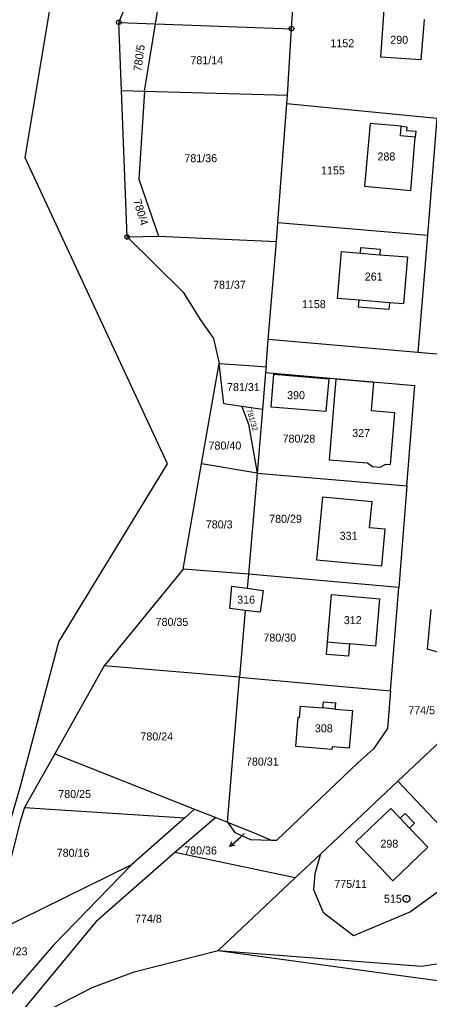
# Model space of a CAD drawing. Extents: x -593358 to -590116, y -1072518 to -1068420.
# Drawn here: x -592030.1 to -591943, y -1070910.9 to -1070702.8 of the extents above; entities that cross this region are included whole.
import ezdxf

# ---------------------------------------------------------------- set-up
doc = ezdxf.new("R2010")
doc.units = 0
for name, color, linetype in [('Parcela KN', 7, 'Continuous'), ('Parcela ZE', 7, 'Continuous'), ('Parcelní číslo', 7, 'Continuous'), ('Parcelní číslo_stavební', 7, 'Continuous'), ('stavby - vnitřní kresba', 7, 'Continuous'), ('Vrstva 16', 7, 'Continuous'), ('Vrstva 17', 7, 'Continuous'), ('Vrstva 24', 7, 'Continuous')]:
    doc.layers.add(name, color=color, linetype=linetype)

msp = doc.modelspace()

# ---------------------------------------------------------------- linework, layer by layer
at = {"layer": 'Parcela KN'}
for p, q in [((-592028.89, -1070732.12), (-592020.01, -1070678.53)), ((-592009.01, -1070703.37), (-592003.67, -1070690.55)), ((-592001.19, -1070703.66), (-591999.04, -1070690.74)), ((-591972.33, -1070704.72), (-591971.79, -1070695.88)), ((-591953.33, -1070710.74), (-591952.61, -1070700.67)), ((-592008.44, -1070717.83), (-592009.01, -1070703.37)), ((-592009.01, -1070703.37), (-592001.19, -1070703.66)), ((-592003.58, -1070717.97), (-592001.19, -1070703.66)), ((-592001.19, -1070703.66), (-591972.33, -1070704.72)), ((-591944.17, -1070702.78), (-591944.88, -1070711.36)), ((-591973.2, -1070718.85), (-591972.33, -1070704.72)), ((-591944.88, -1070711.36), (-591953.33, -1070710.74)), ((-592007.24, -1070748.95), (-592008.44, -1070717.83)), ((-592008.44, -1070717.83), (-592003.58, -1070717.97)), ((-592003.58, -1070717.97), (-592004.78, -1070736.7)), ((-591973.3, -1070720.57), (-591973.2, -1070718.85)), ((-591975.21, -1070745.9), (-591973.3, -1070720.57)), ((-591973.3, -1070720.57), (-591941.43, -1070723.73)), ((-591941.43, -1070723.73), (-591943.47, -1070748.59)), ((-591955.65, -1070724.87), (-591956.79, -1070738.18)), ((-591949.02, -1070725.43), (-591955.65, -1070724.87)), ((-591949.02, -1070725.43), (-591947.84, -1070725.53)), ((-591947.84, -1070725.53), (-591947.91, -1070726.31)), ((-591947.91, -1070726.31), (-591945.95, -1070726.47)), ((-591945.95, -1070726.47), (-591946.05, -1070727.72)), ((-591946.99, -1070739.1), (-591946.05, -1070727.72)), ((-591998.63, -1070797.11), (-592028.89, -1070732.12)), ((-592004.78, -1070736.7), (-592000.6, -1070748.78)), ((-591956.79, -1070738.18), (-591946.99, -1070739.1)), ((-591975.54, -1070749.88), (-591975.21, -1070745.9)), ((-591975.21, -1070745.9), (-591943.47, -1070748.59)), ((-592007.24, -1070748.95), (-592000.6, -1070748.78)), ((-592007.24, -1070748.95), (-591995.35, -1070760.67)), ((-591943.47, -1070748.59), (-591945.51, -1070773.47)), ((-591977.27, -1070770.74), (-591975.54, -1070749.88)), ((-591957.67, -1070752.39), (-591957.58, -1070751.19)), ((-591957.58, -1070751.19), (-591953.48, -1070751.52)), ((-591953.48, -1070751.52), (-591953.58, -1070752.72)), ((-591962.57, -1070762.01), (-591961.67, -1070752.07)), ((-591961.67, -1070752.07), (-591957.67, -1070752.39)), ((-591953.58, -1070752.72), (-591947.68, -1070753.19)), ((-591947.68, -1070753.19), (-591948.53, -1070763.18)), ((-591995.35, -1070760.67), (-591991.75, -1070766.49)), ((-591957.94, -1070762.4), (-591962.57, -1070762.01)), ((-591958.06, -1070763.85), (-591957.94, -1070762.4)), ((-591951.66, -1070764.37), (-591958.06, -1070763.85)), ((-591951.54, -1070762.93), (-591951.66, -1070764.37)), ((-591948.53, -1070763.18), (-591951.54, -1070762.93)), ((-591991.75, -1070766.49), (-591988.9, -1070770.48)), ((-591988.9, -1070770.48), (-591987.72, -1070775.84)), ((-591977.73, -1070776.52), (-591977.27, -1070770.74)), ((-591945.51, -1070773.47), (-591977.27, -1070770.74)), ((-591938.26, -1070774.11), (-591945.51, -1070773.47)), ((-591991.43, -1070797.15), (-591987.72, -1070775.84)), ((-591987.72, -1070775.84), (-591980.35, -1070776.34)), ((-591986.67, -1070784.42), (-591987.72, -1070775.84)), ((-591980.35, -1070776.34), (-591977.73, -1070776.52)), ((-591977.73, -1070776.52), (-591977.84, -1070777.73)), ((-591977.84, -1070777.73), (-591978.5, -1070785.57)), ((-591977.84, -1070777.73), (-591946.12, -1070780.51)), ((-591976.67, -1070785.07), (-591976.09, -1070778.07)), ((-591976.09, -1070778.07), (-591964.41, -1070779.05)), ((-591964.41, -1070779.05), (-591965, -1070786.05)), ((-591962.93, -1070779.16), (-591964.29, -1070796.26)), ((-591954.82, -1070779.87), (-591962.93, -1070779.16)), ((-591955.33, -1070785.89), (-591954.82, -1070779.87)), ((-591947.84, -1070801.82), (-591946.12, -1070780.51)), ((-591982.88, -1070784.95), (-591986.67, -1070784.42)), ((-591978.5, -1070785.57), (-591982.88, -1070784.95)), ((-591982.88, -1070784.95), (-591981.49, -1070788.68)), ((-591978.5, -1070785.57), (-591979.64, -1070799.09)), ((-591965, -1070786.05), (-591976.67, -1070785.07)), ((-591950.4, -1070786.31), (-591955.33, -1070785.89)), ((-591951.31, -1070797.29), (-591950.4, -1070786.31)), ((-591981.49, -1070788.68), (-591979.64, -1070799.09)), ((-592021.75, -1070834.92), (-591998.63, -1070797.11)), ((-591995.32, -1070819.48), (-591991.43, -1070797.15)), ((-591979.64, -1070799.09), (-591991.43, -1070797.15)), ((-591964.29, -1070796.26), (-591956.2, -1070796.89)), ((-591956.2, -1070796.89), (-591955.11, -1070797.68)), ((-591953.5, -1070797.81), (-591952.3, -1070797.2)), ((-591952.3, -1070797.2), (-591951.31, -1070797.29)), ((-591979.64, -1070799.09), (-591981.46, -1070820.57)), ((-591979.64, -1070799.09), (-591947.84, -1070801.82)), ((-591955.11, -1070797.68), (-591953.5, -1070797.81)), ((-591947.84, -1070801.82), (-591949.55, -1070823.39)), ((-591965.76, -1070804.2), (-591967.04, -1070817.5)), ((-591955.22, -1070805.2), (-591965.76, -1070804.2)), ((-591955.74, -1070810.71), (-591955.22, -1070805.2)), ((-591952.44, -1070811.01), (-591955.74, -1070810.71)), ((-591953.17, -1070818.82), (-591952.44, -1070811.01)), ((-591967.04, -1070817.5), (-591953.17, -1070818.82)), ((-591995.32, -1070819.48), (-592012.08, -1070840.02)), ((-591981.46, -1070820.57), (-591995.32, -1070819.48)), ((-591981.46, -1070820.57), (-591981.72, -1070823.56)), ((-591949.55, -1070823.39), (-591981.46, -1070820.57)), ((-591985.45, -1070827.85), (-591985.02, -1070823.1)), ((-591985.02, -1070823.1), (-591981.72, -1070823.56)), ((-591981.72, -1070823.56), (-591978.37, -1070824.02)), ((-591978.37, -1070824.02), (-591978.96, -1070828.67)), ((-591951.33, -1070845.35), (-591949.55, -1070823.39)), ((-591964.69, -1070834.95), (-591963.82, -1070824.9)), ((-591963.82, -1070824.9), (-591953.62, -1070825.78)), ((-591953.62, -1070825.78), (-591954.5, -1070835.89)), ((-591982.14, -1070828.27), (-591985.45, -1070827.85)), ((-591982.14, -1070828.27), (-591983.4, -1070842.44)), ((-591978.96, -1070828.67), (-591982.14, -1070828.27)), ((-591943.42, -1070836.53), (-591942.69, -1070828.05)), ((-592029.91, -1070865.59), (-592021.75, -1070834.92)), ((-591964.89, -1070837.62), (-591964.69, -1070834.95)), ((-591959.98, -1070835.38), (-591960.2, -1070837.97)), ((-591954.5, -1070835.89), (-591959.98, -1070835.38)), ((-591933.56, -1070839.27), (-591943.42, -1070836.53)), ((-591960.2, -1070837.97), (-591964.89, -1070837.62)), ((-592012.08, -1070840.02), (-592022.56, -1070858.71)), ((-591983.4, -1070842.44), (-592012.08, -1070840.02)), ((-591985.92, -1070873.27), (-591983.4, -1070842.44)), ((-591983.4, -1070842.44), (-591951.33, -1070845.35)), ((-591951.33, -1070845.35), (-591951.97, -1070853.34)), ((-591970.64, -1070851), (-591970.44, -1070848.59)), ((-591970.44, -1070848.59), (-591965.65, -1070848.99)), ((-591965.65, -1070848.99), (-591965.54, -1070847.67)), ((-591965.54, -1070847.67), (-591962.98, -1070847.88)), ((-591962.98, -1070847.88), (-591963.09, -1070849.21)), ((-591963.09, -1070849.21), (-591959.38, -1070849.52)), ((-591933.38, -1070849.09), (-591949.74, -1070864.52)), ((-591971.41, -1070857.19), (-591970.92, -1070850.97)), ((-591970.92, -1070850.97), (-591970.64, -1070851)), ((-591959.38, -1070849.52), (-591960.07, -1070857.55)), ((-591951.97, -1070853.34), (-591954.91, -1070857.63)), ((-591963.74, -1070857.83), (-591971.41, -1070857.19)), ((-591963.7, -1070857.27), (-591963.74, -1070857.83)), ((-591960.07, -1070857.55), (-591963.7, -1070857.27)), ((-591954.91, -1070857.63), (-591958.28, -1070860.68)), ((-592022.56, -1070858.71), (-592029, -1070870.12)), ((-592022.56, -1070858.71), (-591992.95, -1070870.47)), ((-591975.43, -1070877.04), (-591958.28, -1070860.68)), ((-592044.25, -1070914.9), (-592029.91, -1070865.59)), ((-591949.74, -1070864.52), (-591966.1, -1070879.95)), ((-591933.14, -1070882.12), (-591949.74, -1070864.52)), ((-592029, -1070870.12), (-592029.94, -1070873.08)), ((-592029, -1070870.12), (-591994.97, -1070872.32)), ((-591992.95, -1070870.47), (-591994.97, -1070872.32)), ((-591992.95, -1070870.47), (-591988.4, -1070872.28)), ((-591958.68, -1070877.44), (-591951.21, -1070870.32)), ((-591951.21, -1070870.32), (-591949.22, -1070872.42)), ((-591949.22, -1070872.42), (-591948.17, -1070871.42)), ((-591948.17, -1070871.42), (-591946.21, -1070873.48)), ((-592029.94, -1070873.08), (-592035.98, -1070896.91)), ((-591994.97, -1070872.32), (-592006.31, -1070882.3)), ((-591988.4, -1070872.28), (-591997.11, -1070879.7)), ((-591988.4, -1070872.28), (-591985.92, -1070873.27)), ((-591985.92, -1070873.27), (-591979.74, -1070875.73)), ((-591985.92, -1070873.27), (-591984.38, -1070875.46)), ((-591946.21, -1070873.48), (-591947.26, -1070874.48)), ((-591984.38, -1070875.46), (-591981.05, -1070876.94)), ((-591979.74, -1070875.73), (-591976.67, -1070877.09)), ((-591947.26, -1070874.48), (-591943.38, -1070878.56)), ((-591981.05, -1070876.94), (-591976.67, -1070877.09)), ((-591976.67, -1070877.09), (-591975.43, -1070877.04)), ((-591950.79, -1070885.67), (-591958.68, -1070877.44)), ((-591997.11, -1070879.7), (-592013.86, -1070894.42)), ((-591971.53, -1070885.07), (-591997.11, -1070879.7)), ((-591966.1, -1070879.95), (-591971.53, -1070885.07)), ((-591967.29, -1070884.16), (-591966.1, -1070879.95)), ((-591943.38, -1070878.56), (-591950.79, -1070885.67)), ((-592006.31, -1070882.3), (-592035.98, -1070896.91)), ((-592006.31, -1070882.3), (-592022.86, -1070899.35)), ((-591933.14, -1070882.12), (-591947.02, -1070892.31)), ((-591967.58, -1070887.6), (-591967.29, -1070884.16)), ((-591971.53, -1070885.07), (-591987.92, -1070900.52)), ((-591965.5, -1070892.49), (-591967.58, -1070887.6)), ((-591959.15, -1070897.39), (-591965.5, -1070892.49)), ((-591947.02, -1070892.31), (-591959.15, -1070897.39)), ((-592013.86, -1070894.42), (-592035.77, -1070920.86)), ((-592022.86, -1070899.35), (-592039.31, -1070918.31)), ((-592005.73, -1070905.04), (-591987.92, -1070900.52)), ((-591987.92, -1070900.52), (-591944.69, -1070903.85)), ((-591987.92, -1070900.52), (-591939.74, -1070907.08)), ((-591944.69, -1070903.85), (-591916.89, -1070899.35)), ((-592014.65, -1070908.37), (-592005.73, -1070905.04)), ((-592025.24, -1070913.83), (-592014.65, -1070908.37))]:
    msp.add_line(p, q, dxfattribs=at)
at = {"layer": 'Parcela ZE'}
for p, q in [((-592003.58, -1070717.97), (-591973.2, -1070718.85)), ((-592000.6, -1070748.78), (-591975.54, -1070749.88))]:
    msp.add_line(p, q, dxfattribs=at)
at = {"layer": 'stavby - vnitřní kresba'}
for p, q in [((-591949.2, -1070727.45), (-591949.02, -1070725.43)), ((-591946.05, -1070727.72), (-591949.2, -1070727.45)), ((-591957.67, -1070752.39), (-591953.58, -1070752.72)), ((-591951.54, -1070762.93), (-591957.94, -1070762.4)), ((-591964.69, -1070834.95), (-591959.98, -1070835.38)), ((-591963.09, -1070849.21), (-591965.65, -1070848.99)), ((-591949.22, -1070872.42), (-591947.26, -1070874.48))]:
    msp.add_line(p, q, dxfattribs=at)
at = {"layer": 'Vrstva 16'}
for p in [(-591985.435, -1070878.4), (-591982.42, -1070875.73)]:
    msp.add_line(p, (-591983.19, -1070876.41), dxfattribs=at)
msp.add_lwpolyline([(-591984.355, -1070878.111), (-591985.435, -1070878.4), (-591985.018, -1070877.362)], dxfattribs=at)
at = {"layer": 'Vrstva 24'}
for p, q in [((-592009.13, -1070703.37), (-592008.89, -1070703.37)), ((-591972.45, -1070704.72), (-591972.21, -1070704.72)), ((-592007.36, -1070748.95), (-592007.12, -1070748.95)), ((-591947.95, -1070889.5), (-591947.85, -1070889.5))]:
    msp.add_line(p, q, dxfattribs=at)
for points in [[(-592008.86, -1070702.89), (-592008.61, -1070703.07), (-592008.51, -1070703.36), (-592008.61, -1070703.65), (-592008.86, -1070703.83), (-592009.17, -1070703.83), (-592009.42, -1070703.65), (-592009.52, -1070703.36), (-592009.42, -1070703.07), (-592009.17, -1070702.89)], [(-591972.18, -1070704.24), (-591971.93, -1070704.42), (-591971.83, -1070704.71), (-591971.93, -1070705), (-591972.18, -1070705.18), (-591972.49, -1070705.18), (-591972.74, -1070705), (-591972.84, -1070704.71), (-591972.74, -1070704.42), (-591972.49, -1070704.24)], [(-592007.09, -1070748.47), (-592006.84, -1070748.65), (-592006.74, -1070748.94), (-592006.84, -1070749.23), (-592007.09, -1070749.41), (-592007.4, -1070749.41), (-592007.65, -1070749.23), (-592007.75, -1070748.94), (-592007.65, -1070748.65), (-592007.4, -1070748.47)], [(-591947.71, -1070888.78), (-591947.37, -1070888.97), (-591947.18, -1070889.31), (-591947.18, -1070889.7), (-591947.37, -1070890.04), (-591947.71, -1070890.23), (-591948.1, -1070890.23), (-591948.44, -1070890.04), (-591948.63, -1070889.7), (-591948.63, -1070889.31), (-591948.44, -1070888.97), (-591948.1, -1070888.78)]]:
    msp.add_lwpolyline(points, close=True, dxfattribs=at)

# ---------------------------------------------------------------- texts
at = {"layer": 'Parcelní číslo'}
for s, height, p in [('1152', 1.7, (-591964.058, -1070708.65)), ('781/14', 1.7, (-591993.793, -1070712.26)), ('781/36', 1.7, (-591995.068, -1070733.07)), ('1155', 1.7, (-591966.051, -1070735.66)), ('781/37', 1.7, (-591988.988, -1070759.94)), ('1158', 1.7, (-591970.114, -1070764.07)), ('781/31', 1.7, (-591986.02, -1070781.68)), ('780/28', 1.7, (-591974.22, -1070792.63)), ('780/40', 1.7, (-591989.943, -1070794.1)), ('780/3', 1.7, (-591990.524, -1070810.85)), ('780/29', 1.7, (-591977.069, -1070809.66)), ('780/35', 1.7, (-592001.19, -1070831.55)), ('780/30', 1.7, (-591978.29, -1070834.89)), ('774/5', 1.7, (-591947.53, -1070850.32)), ('780/24', 1.7, (-592004.419, -1070855.88)), ('780/31', 1.7, (-591981.995, -1070861.22)), ('780/25', 1.7, (-592021.866, -1070868.1)), ('780/36', 0.1, (-591982.668, -1070875.73)), ('780/16', 1.7, (-592022.188, -1070880.59)), ('775/11', 1.7, (-591963.243, -1070887.21)), ('774/8', 1.7, (-592005.563, -1070894.58)), ('780/23', 1.7, (-592035.346, -1070901.52))]:
    msp.add_text(s, height=height, dxfattribs=at).set_placement(p)
for s, height, rotation, p in [('780/5', 1.7, 82.44863, (-592004.219, -1070713.863)), ('780/4', 1.7, 286.53619, (-592005.951, -1070741.206)), ('781/32', 1.14, 286.59349, (-591981.901, -1070785.65))]:
    msp.add_text(s, height=height, rotation=rotation, dxfattribs=at).set_placement(p)
at = {"layer": 'Parcelní číslo_stavební'}
for s, p in [('290', (-591951.345, -1070707.93)), ('288', (-591954.065, -1070732.71)), ('261', (-591956.76, -1070758.21)), ('390', (-591973.258, -1070783.4)), ('327', (-591959.425, -1070791.44)), ('331', (-591962.1, -1070813.27)), ('316', (-591983.853, -1070826.83)), ('312', (-591961.207, -1070831.18)), ('308', (-591967.358, -1070854.15)), ('298', (-591953.438, -1070878.66))]:
    msp.add_text(s, height=1.7, dxfattribs=at).set_placement(p)
at = {"layer": 'Vrstva 16'}
msp.add_text('780/36', height=1.7, dxfattribs=at).set_placement((-591995.114, -1070880.1))
at = {"layer": 'Vrstva 17'}
msp.add_text('515', height=1.7, dxfattribs=at).set_placement((-591952.69, -1070890.35))

doc.saveas('drawing.dxf')
